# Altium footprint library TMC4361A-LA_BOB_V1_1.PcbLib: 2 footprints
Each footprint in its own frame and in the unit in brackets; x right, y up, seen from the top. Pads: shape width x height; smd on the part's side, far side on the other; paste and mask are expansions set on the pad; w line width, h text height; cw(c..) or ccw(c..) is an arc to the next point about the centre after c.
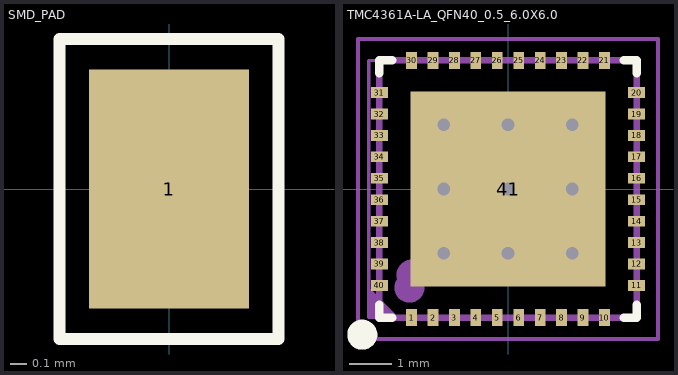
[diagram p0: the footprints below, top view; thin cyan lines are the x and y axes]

## SMD_PAD [mm]
pads (1):
  rect 1x1.5 smd: 1(0,0)
Top Overlay:
  lines w0.076: -0.686,-0.94 0.686,-0.94 0.686,0.94 -0.686,0.94 -0.686,-0.94

## TMC4361A-LA_QFN40_0.5_6.0X6.0 [mm]
pads (41):
  rect 0.25x0.4 smd: 1(-2.25,-3) 2(-1.75,-3) 3(-1.25,-3) 4(-0.75,-3) 5(-0.25,-3) 6(0.25,-3) 7(0.75,-3) 8(1.25,-3) 9(1.75,-3) 10(2.25,-3) 21(2.25,3) 22(1.75,3) 23(1.25,3) 24(0.75,3) 25(0.25,3) 26(-0.25,3) 27(-0.75,3) 28(-1.25,3) 29(-1.75,3) 30(-2.25,3)
  rect 0.4x0.25 smd: 11(3,-2.25) 12(3,-1.75) 13(3,-1.25) 14(3,-0.75) 15(3,-0.25) 16(3,0.25) 17(3,0.75) 18(3,1.25) 19(3,1.75) 20(3,2.25) 31(-3,2.25) 32(-3,1.75) 33(-3,1.25) 34(-3,0.75) 35(-3,0.25) 36(-3,-0.25) 37(-3,-0.75) 38(-3,-1.25) 39(-3,-1.75) 40(-3,-2.25)
  rect 4.55x4.55 smd paste-25.4: 41(0,0)
via 1.5,-1.5 diameter 0.757 hole 0.3
via 0,-1.5 diameter 0.757 hole 0.3
via -1.5,-1.5 diameter 0.757 hole 0.3
via -1.5,1.5 diameter 0.757 hole 0.3
via 0,1.5 diameter 0.757 hole 0.3
via 1.5,1.5 diameter 0.757 hole 0.3
via 1.5,0 diameter 0.757 hole 0.3
via -1.5,0 diameter 0.757 hole 0.3
via 0,0 diameter 0.757 hole 0.3
Top Overlay:
  circle w0.5: c-3.4,-3.4 r0.1
  lines w0.2: -3,-2.7 -3,-3 -2.7,-3 ; -3,2.7 -3,3 -2.7,3 ; 2.7,-3 3,-3 3,-2.7 ; 2.7,3 3,3 3,2.7
Top Paste:
  region: 0.875,0.575 2.025,0.575 2.025,-0.575 0.875,-0.575
  region: 0.875,2.025 2.025,2.025 2.025,0.875 0.875,0.875
  region: -0.575,2.025 0.575,2.025 0.575,0.875 -0.575,0.875
  region: -0.575,0.575 0.575,0.575 0.575,-0.575 -0.575,-0.575
  region: -0.575,-0.875 0.575,-0.875 0.575,-2.025 -0.575,-2.025
  region: 0.875,-0.875 2.025,-0.875 2.025,-2.025 0.875,-2.025
  region: -2.025,-0.875 -0.875,-0.875 -0.875,-2.025 -2.025,-2.025
  region: -2.025,0.575 -0.875,0.575 -0.875,-0.575 -2.025,-0.575
  region: -2.025,2.025 -0.875,2.025 -0.875,0.875 -2.025,0.875
Bottom Solder:
  region: -2.1,2.1 -2.1,-2.1 2.1,-2.1 2.1,2.1
Mechanical 13:
  circle w0.5: c-2.3,-2.3 r0.1
  lines w0.15: -3,-3 3,-3 3,3 -3,3 -3,-3
Mechanical 15:
  lines w0.1: -3.5,-3.5 3.5,-3.5 3.5,3.5 -3.5,3.5 -3.5,-3.5
TopAsm:
  circle w0.5: c-2.25,-2 r0.1
  region: -3.25,-2.294 -2.544,-3 -3.25,-3
  lines w0.076: -3.25,-3 3,-3 3,3 -3.25,3 -3.25,-3
  text ".Designator" at -2,-0.5 h1.27
3D body: height 0.9, standoff 0, extent -3,-3 3,3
